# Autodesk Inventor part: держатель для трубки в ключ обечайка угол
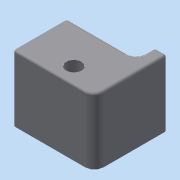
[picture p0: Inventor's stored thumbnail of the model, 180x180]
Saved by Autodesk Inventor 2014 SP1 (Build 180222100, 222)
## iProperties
Created: 2015-10
Part Number: держатель для трубки в ключ обечайка угол
Material: Типовые
Document SubType Name: Modeling
Designer: hals
Density: 1 g/cm^3
Appearance: По умолчанию
Author: hals
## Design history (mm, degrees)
node "РабПлоскость1"
sketch "Эскиз1"
  geometry: L1 (2, -79.959)-(148.131, -79.959); L2 (150.131, -77.959)-(150.131, -64.039); L3 (0, -64.039)-(0, -77.959); L4 (0, -79.959)-(150.131, 2.427); L5 (150.131, -79.959)-(0, 2.427); L6 (2.5, -64.039)-(2.5, -72.369); L7 (4.5, -74.369)-(145.5, -74.369); L8 (147.5, -72.369)-(147.5, -64.039); L9 (0, -64.039)-(2.5, -64.039); L10 (147.5, -64.039)-(150.131, -64.039); A1 r 2 centre (2, -77.959) between (0, -77.959) and (2, -79.959); A2 r 2 centre (148.131, -77.959) between (148.131, -79.959) and (150.131, -77.959); A3 r 2 centre (4.5, -72.369) between (2.5, -72.369) and (4.5, -74.369); A4 r 2 centre (145.5, -72.369) between (145.5, -74.369) and (147.5, -72.369); 3 further points
  constraints: 20 end point, 9 point on line, 8 point on circle, 8 tangent, 4 centre point, 3 parallel, 2 equal radius, 2 perpendicular, 1 horizontal
  dimensions: "d0" = 2 radius of A1; "d1" = 145 distance of point (2.5, -74.369) point (147.5, -74.369); "d2" = 2.5 distance between parallel lines of L6 L3; "d4" = 2 radius of A3
extrude "Выдавливание1" new body sketch "Эскиз1" distance "d5" = 13; taper "d6" = 0 deg
sketch "Эскиз2"
  geometry: L1 (2, -79.959)-(148.131, -79.959) reference; L2 (150.131, -77.959)-(150.131, -64.039) reference; L3 (150.131, -64.039)-(147.5, -64.039) reference; L4 (147.5, -64.039)-(147.5, -72.369) reference; L5 (145.5, -74.369)-(4.5, -74.369) reference; L6 (2.5, -72.369)-(2.5, -64.039) reference; L7 (2.5, -64.039)-(0, -64.039) reference; L8 (0, -64.039)-(0, -77.959) reference; L9 (2.5, -68.204)-(147.5, -68.204); A1 r 2 centre (148.131, -77.959) between (148.131, -79.959) and (150.131, -77.959) reference; A2 r 2 centre (145.5, -72.369) between (145.5, -74.369) and (147.5, -72.369) reference; A3 r 2 centre (4.5, -72.369) between (2.5, -72.369) and (4.5, -74.369) reference; A4 r 2 centre (2, -77.959) between (0, -77.959) and (2, -79.959) reference; 1 further point
  constraints: 2 end point, 2 midpoint
extrude "Выдавливание2" join sketch "Эскиз2" distance "d7" = 1.5; taper "d8" = 0 deg
fillet "Сопряжение1" dims "d9" = 2
fillet "Сопряжение2" dims "d10" = 0.5
fillet "Сопряжение3" dims "d11" = 0.5
node "Отверстие3"
node "Отверстие5"
sketch "Эскиз6"
  geometry: L1 (132.277, -59.879)-(-7.87, -59.879); L2 (-7.87, -59.879)-(-7.87, -89.103); L3 (-7.87, -89.103)-(132.277, -89.103); L4 (132.277, -89.103)-(132.277, -59.879); C1 r 1.7 at (8, -76.459) reference; 1 further point
  constraints: 8 end point, 2 parallel, 1 horizontal, 1 perpendicular
extrude "Выдавливание3" cut sketch "Эскиз6" distance "d33" = 22.75; taper "d34" = 0 deg
fillet "Сопряжение4" dims "d35" = 0.5
node "Твердое тело1"
sketch "Эскиз4"
  geometry: 1 further point
hole "Отверстие2" sketch "Эскиз4" diameter "d19" = 3.4; stored, may be unused: countersink angle "d23" = 90 deg, drill point angle "d25" = 0 deg; dims "d20" = 6, "d21" = 4, "d22" = 2, "d24" = 8
sketch "Эскиз5"
  geometry: 1 further point
hole "Отверстие4" sketch "Эскиз5" diameter "d26" = 3.4; stored, may be unused: countersink angle "d30" = 90 deg, drill point angle "d32" = 0 deg; dims "d27" = 6, "d28" = 4, "d29" = 2, "d31" = 8
